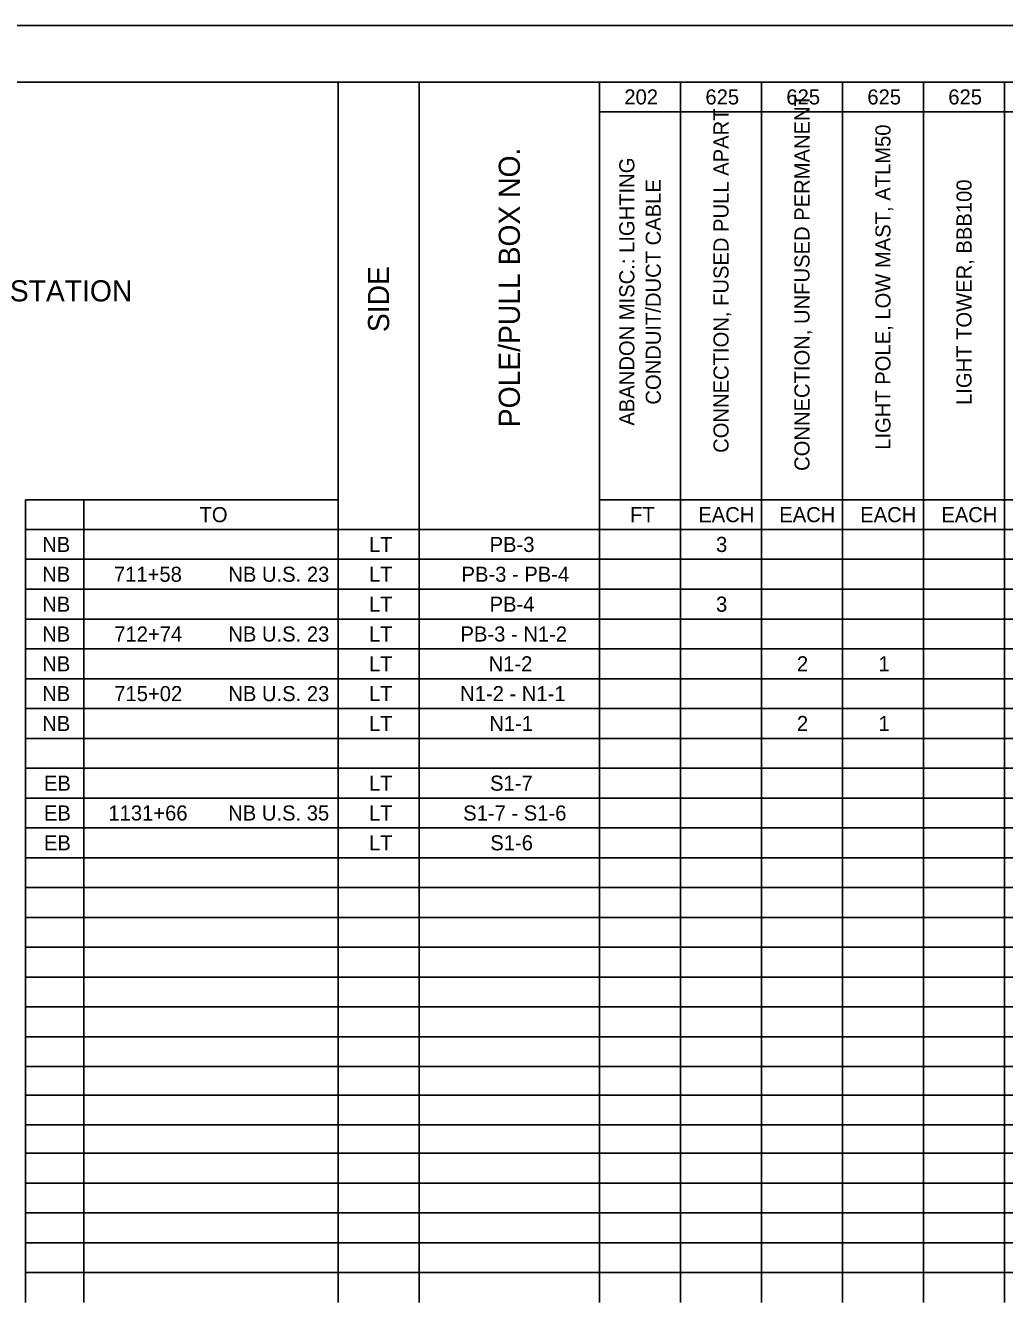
# Model space of a CAD drawing. Extents: x 0 to 34, y 0 to 22.
# Drawn here: x 4.68 to 13.35, y 10.69 to 22 of the extents above; entities that cross this region are included whole.
import ezdxf

# ---------------------------------------------------------------- set-up
doc = ezdxf.new("R2010")
doc.units = 0
for name, color, linetype in [('SH_Border', 7, 'Continuous'), ('SH_Cut_Line', 7, 'Continuous'), ('SH_Text', 7, 'Continuous')]:
    doc.layers.add(name, color=color, linetype=linetype)

msp = doc.modelspace()

# ---------------------------------------------------------------- linework, layer by layer
at = {"layer": 'SH_Border'}
msp.add_lwpolyline([(1.5, 21.5), (33.5, 21.5), (33.5, 0.5), (1.5, 0.5)], close=True, dxfattribs=at)
at = {"layer": 'SH_Cut_Line'}
msp.add_lwpolyline([(0, 0), (34, 0), (34, 22), (0, 22)], close=True, dxfattribs=at)
at = {"layer": 'SH_Text'}
for p, q in [((4.683, 21.5), (11.918, 21.5)), ((7.451, 21.5), (7.451, 21.236)), ((8.168, 21.5), (8.168, 21.236)), ((9.766, 21.5), (9.766, 21.236)), ((10.484, 21.5), (10.484, 21.236)), ((11.201, 21.5), (11.201, 21.236)), ((11.918, 21.5), (12.635, 21.5)), ((11.918, 21.5), (11.918, 21.236)), ((12.635, 21.5), (13.352, 21.5)), ((12.635, 21.5), (12.635, 21.236)), ((13.352, 21.5), (14.069, 21.5)), ((13.352, 21.5), (13.352, 21.236)), ((7.451, 21.236), (7.451, 20.972)), ((8.168, 21.236), (8.168, 20.972)), ((9.766, 21.236), (11.918, 21.236)), ((9.766, 21.236), (9.766, 20.972)), ((10.484, 21.236), (10.484, 20.972)), ((11.201, 21.236), (11.201, 20.972)), ((11.918, 21.236), (12.635, 21.236)), ((11.918, 21.236), (11.918, 20.972)), ((12.635, 21.236), (13.352, 21.236)), ((12.635, 21.236), (12.635, 20.972)), ((13.352, 21.236), (14.069, 21.236)), ((13.352, 21.236), (13.352, 20.972)), ((7.451, 20.972), (7.451, 20.707)), ((8.168, 20.972), (8.168, 20.707)), ((9.766, 20.972), (9.766, 20.707)), ((10.484, 20.972), (10.484, 20.707)), ((11.201, 20.972), (11.201, 20.707)), ((11.918, 20.972), (11.918, 20.707)), ((12.635, 20.972), (12.635, 20.707)), ((13.352, 20.972), (13.352, 20.707)), ((7.451, 20.707), (7.451, 20.443)), ((8.168, 20.707), (8.168, 20.443)), ((9.766, 20.707), (9.766, 20.443)), ((10.484, 20.707), (10.484, 20.443)), ((11.201, 20.707), (11.201, 20.443)), ((11.918, 20.707), (11.918, 20.443)), ((12.635, 20.707), (12.635, 20.443)), ((13.352, 20.707), (13.352, 20.443)), ((7.451, 20.443), (7.451, 20.179)), ((8.168, 20.443), (8.168, 20.179)), ((9.766, 20.443), (9.766, 20.179)), ((10.484, 20.443), (10.484, 20.179)), ((11.201, 20.443), (11.201, 20.179)), ((11.918, 20.443), (11.918, 20.179)), ((12.635, 20.443), (12.635, 20.179)), ((13.352, 20.443), (13.352, 20.179)), ((7.451, 20.179), (7.451, 19.915)), ((8.168, 20.179), (8.168, 19.915)), ((9.766, 20.179), (9.766, 19.915)), ((10.484, 20.179), (10.484, 19.915)), ((11.201, 20.179), (11.201, 19.915)), ((11.918, 20.179), (11.918, 19.915)), ((12.635, 20.179), (12.635, 19.915)), ((13.352, 20.179), (13.352, 19.915)), ((7.451, 19.915), (7.451, 19.651)), ((8.168, 19.915), (8.168, 19.651)), ((9.766, 19.915), (9.766, 19.651)), ((10.484, 19.915), (10.484, 19.651)), ((11.201, 19.915), (11.201, 19.651)), ((11.918, 19.915), (11.918, 19.651)), ((12.635, 19.915), (12.635, 19.651)), ((13.352, 19.915), (13.352, 19.651)), ((7.451, 19.651), (7.451, 19.386)), ((8.168, 19.651), (8.168, 19.386)), ((9.766, 19.651), (9.766, 19.386)), ((10.484, 19.651), (10.484, 19.386)), ((11.201, 19.651), (11.201, 19.386)), ((11.918, 19.651), (11.918, 19.386)), ((12.635, 19.651), (12.635, 19.386)), ((13.352, 19.651), (13.352, 19.386)), ((7.451, 19.386), (7.451, 19.122)), ((8.168, 19.386), (8.168, 19.122)), ((9.766, 19.386), (9.766, 19.122)), ((10.484, 19.386), (10.484, 19.122)), ((11.201, 19.386), (11.201, 19.122)), ((11.918, 19.386), (11.918, 19.122)), ((12.635, 19.386), (12.635, 19.122)), ((13.352, 19.386), (13.352, 19.122)), ((7.451, 19.122), (7.451, 18.858)), ((8.168, 19.122), (8.168, 18.858)), ((9.766, 19.122), (9.766, 18.858)), ((10.484, 19.122), (10.484, 18.858)), ((11.201, 19.122), (11.201, 18.858)), ((11.918, 19.122), (11.918, 18.858)), ((12.635, 19.122), (12.635, 18.858)), ((13.352, 19.122), (13.352, 18.858)), ((7.451, 18.858), (7.451, 18.594)), ((8.168, 18.858), (8.168, 18.594)), ((9.766, 18.858), (9.766, 18.594)), ((10.484, 18.858), (10.484, 18.594)), ((11.201, 18.858), (11.201, 18.594)), ((11.918, 18.858), (11.918, 18.594)), ((12.635, 18.858), (12.635, 18.594)), ((13.352, 18.858), (13.352, 18.594)), ((7.451, 18.594), (7.451, 18.329)), ((8.168, 18.594), (8.168, 18.329)), ((9.766, 18.594), (9.766, 18.329)), ((10.484, 18.594), (10.484, 18.329)), ((11.201, 18.594), (11.201, 18.329)), ((11.918, 18.594), (11.918, 18.329)), ((12.635, 18.594), (12.635, 18.329)), ((13.352, 18.594), (13.352, 18.329)), ((7.451, 18.329), (7.451, 18.065)), ((8.168, 18.329), (8.168, 18.065)), ((9.766, 18.329), (9.766, 18.065)), ((10.484, 18.329), (10.484, 18.065)), ((11.201, 18.329), (11.201, 18.065)), ((11.918, 18.329), (11.918, 18.065)), ((12.635, 18.329), (12.635, 18.065)), ((13.352, 18.329), (13.352, 18.065)), ((7.451, 18.065), (7.451, 17.801)), ((8.168, 18.065), (8.168, 17.801)), ((9.766, 18.065), (9.766, 17.801)), ((10.484, 18.065), (10.484, 17.801)), ((11.201, 18.065), (11.201, 17.801)), ((11.918, 18.065), (11.918, 17.801)), ((12.635, 18.065), (12.635, 17.801)), ((13.352, 18.065), (13.352, 17.801)), ((4.683, 17.801), (7.451, 17.801)), ((4.683, 17.801), (4.683, 17.537)), ((5.199, 17.801), (5.199, 17.537)), ((7.451, 17.801), (7.451, 17.537)), ((8.168, 17.801), (8.168, 17.537)), ((9.766, 17.801), (11.918, 17.801)), ((9.766, 17.801), (9.766, 17.537)), ((10.484, 17.801), (10.484, 17.537)), ((11.201, 17.801), (11.201, 17.537)), ((11.918, 17.801), (12.635, 17.801)), ((11.918, 17.801), (11.918, 17.537)), ((12.635, 17.801), (13.352, 17.801)), ((12.635, 17.801), (12.635, 17.537)), ((13.352, 17.801), (14.069, 17.801)), ((13.352, 17.801), (13.352, 17.537)), ((4.683, 17.537), (11.918, 17.537)), ((4.683, 17.537), (4.683, 17.273)), ((5.199, 17.537), (5.199, 17.273)), ((7.451, 17.537), (7.451, 17.273)), ((8.168, 17.537), (8.168, 17.273)), ((9.766, 17.537), (9.766, 17.273)), ((10.484, 17.537), (10.484, 17.273)), ((11.201, 17.537), (11.201, 17.273)), ((11.918, 17.537), (12.635, 17.537)), ((11.918, 17.537), (11.918, 17.273)), ((12.635, 17.537), (13.352, 17.537)), ((12.635, 17.537), (12.635, 17.273)), ((13.352, 17.537), (14.069, 17.537)), ((13.352, 17.537), (13.352, 17.273)), ((4.683, 17.273), (11.918, 17.273)), ((4.683, 17.273), (4.683, 17.008)), ((5.199, 17.273), (5.199, 17.008)), ((7.451, 17.273), (7.451, 17.008)), ((8.168, 17.273), (8.168, 17.008)), ((9.766, 17.273), (9.766, 17.008)), ((10.484, 17.273), (10.484, 17.008)), ((11.201, 17.273), (11.201, 17.008)), ((11.918, 17.273), (12.635, 17.273)), ((11.918, 17.273), (11.918, 17.008)), ((12.635, 17.273), (13.352, 17.273)), ((12.635, 17.273), (12.635, 17.008)), ((13.352, 17.273), (14.069, 17.273)), ((13.352, 17.273), (13.352, 17.008)), ((4.683, 17.008), (11.918, 17.008)), ((4.683, 17.008), (4.683, 16.744)), ((5.199, 17.008), (5.199, 16.744)), ((7.451, 17.008), (7.451, 16.744)), ((8.168, 17.008), (8.168, 16.744)), ((9.766, 17.008), (9.766, 16.744)), ((10.484, 17.008), (10.484, 16.744)), ((11.201, 17.008), (11.201, 16.744)), ((11.918, 17.008), (12.635, 17.008)), ((11.918, 17.008), (11.918, 16.744)), ((12.635, 17.008), (13.352, 17.008)), ((12.635, 17.008), (12.635, 16.744)), ((13.352, 17.008), (14.069, 17.008)), ((13.352, 17.008), (13.352, 16.744)), ((4.683, 16.744), (11.918, 16.744)), ((4.683, 16.744), (4.683, 16.48)), ((5.199, 16.744), (5.199, 16.48)), ((7.451, 16.744), (7.451, 16.48)), ((8.168, 16.744), (8.168, 16.48)), ((9.766, 16.744), (9.766, 16.48)), ((10.484, 16.744), (10.484, 16.48)), ((11.201, 16.744), (11.201, 16.48)), ((11.918, 16.744), (12.635, 16.744)), ((11.918, 16.744), (11.918, 16.48)), ((12.635, 16.744), (13.352, 16.744)), ((12.635, 16.744), (12.635, 16.48)), ((13.352, 16.744), (14.069, 16.744)), ((13.352, 16.744), (13.352, 16.48)), ((4.683, 16.48), (11.918, 16.48)), ((4.683, 16.48), (4.683, 16.216)), ((5.199, 16.48), (5.199, 16.216)), ((7.451, 16.48), (7.451, 16.216)), ((8.168, 16.48), (8.168, 16.216)), ((9.766, 16.48), (9.766, 16.216)), ((10.484, 16.48), (10.484, 16.216)), ((11.201, 16.48), (11.201, 16.216)), ((11.918, 16.48), (12.635, 16.48)), ((11.918, 16.48), (11.918, 16.216)), ((12.635, 16.48), (13.352, 16.48)), ((12.635, 16.48), (12.635, 16.216)), ((13.352, 16.48), (14.069, 16.48)), ((13.352, 16.48), (13.352, 16.216)), ((4.683, 16.216), (11.918, 16.216)), ((4.683, 16.216), (4.683, 15.951)), ((5.199, 16.216), (5.199, 15.951)), ((7.451, 16.216), (7.451, 15.951)), ((8.168, 16.216), (8.168, 15.951)), ((9.766, 16.216), (9.766, 15.951)), ((10.484, 16.216), (10.484, 15.951)), ((11.201, 16.216), (11.201, 15.951)), ((11.918, 16.216), (12.635, 16.216)), ((11.918, 16.216), (11.918, 15.951)), ((12.635, 16.216), (13.352, 16.216)), ((12.635, 16.216), (12.635, 15.951)), ((13.352, 16.216), (14.069, 16.216)), ((13.352, 16.216), (13.352, 15.951)), ((4.683, 15.951), (11.918, 15.951)), ((4.683, 15.951), (4.683, 15.687)), ((5.199, 15.951), (5.199, 15.687)), ((7.451, 15.951), (7.451, 15.687)), ((8.168, 15.951), (8.168, 15.687)), ((9.766, 15.951), (9.766, 15.687)), ((10.484, 15.951), (10.484, 15.687)), ((11.201, 15.951), (11.201, 15.687)), ((11.918, 15.951), (12.635, 15.951)), ((11.918, 15.951), (11.918, 15.687)), ((12.635, 15.951), (13.352, 15.951)), ((12.635, 15.951), (12.635, 15.687)), ((13.352, 15.951), (14.069, 15.951)), ((13.352, 15.951), (13.352, 15.687)), ((4.683, 15.687), (11.918, 15.687)), ((4.683, 15.687), (4.683, 15.423)), ((5.199, 15.687), (5.199, 15.423)), ((7.451, 15.687), (7.451, 15.423)), ((8.168, 15.687), (8.168, 15.423)), ((9.766, 15.687), (9.766, 15.423)), ((10.484, 15.687), (10.484, 15.423)), ((11.201, 15.687), (11.201, 15.423)), ((11.918, 15.687), (12.635, 15.687)), ((11.918, 15.687), (11.918, 15.423)), ((12.635, 15.687), (13.352, 15.687)), ((12.635, 15.687), (12.635, 15.423)), ((13.352, 15.687), (14.069, 15.687)), ((13.352, 15.687), (13.352, 15.423)), ((4.683, 15.423), (11.918, 15.423)), ((4.683, 15.423), (4.683, 15.159)), ((5.199, 15.423), (5.199, 15.159)), ((7.451, 15.423), (7.451, 15.159)), ((8.168, 15.423), (8.168, 15.159)), ((9.766, 15.423), (9.766, 15.159)), ((10.484, 15.423), (10.484, 15.159)), ((11.201, 15.423), (11.201, 15.159)), ((11.918, 15.423), (12.635, 15.423)), ((11.918, 15.423), (11.918, 15.159)), ((12.635, 15.423), (13.352, 15.423)), ((12.635, 15.423), (12.635, 15.159)), ((13.352, 15.423), (14.069, 15.423)), ((13.352, 15.423), (13.352, 15.159)), ((4.683, 15.159), (11.918, 15.159)), ((4.683, 15.159), (4.683, 14.895)), ((5.199, 15.159), (5.199, 14.895)), ((7.451, 15.159), (7.451, 14.895)), ((8.168, 15.159), (8.168, 14.895)), ((9.766, 15.159), (9.766, 14.895)), ((10.484, 15.159), (10.484, 14.895)), ((11.201, 15.159), (11.201, 14.895)), ((11.918, 15.159), (12.635, 15.159)), ((11.918, 15.159), (11.918, 14.895)), ((12.635, 15.159), (13.352, 15.159)), ((12.635, 15.159), (12.635, 14.895)), ((13.352, 15.159), (14.069, 15.159)), ((13.352, 15.159), (13.352, 14.895)), ((4.683, 14.895), (11.918, 14.895)), ((4.683, 14.895), (4.683, 14.63)), ((5.199, 14.895), (5.199, 14.63)), ((7.451, 14.895), (7.451, 14.63)), ((8.168, 14.895), (8.168, 14.63)), ((9.766, 14.895), (9.766, 14.63)), ((10.484, 14.895), (10.484, 14.63)), ((11.201, 14.895), (11.201, 14.63)), ((11.918, 14.895), (12.635, 14.895)), ((11.918, 14.895), (11.918, 14.63)), ((12.635, 14.895), (13.352, 14.895)), ((12.635, 14.895), (12.635, 14.63)), ((13.352, 14.895), (14.069, 14.895)), ((13.352, 14.895), (13.352, 14.63)), ((4.683, 14.63), (11.918, 14.63)), ((4.683, 14.63), (4.683, 14.366)), ((5.199, 14.63), (5.199, 14.366)), ((7.451, 14.63), (7.451, 14.366)), ((8.168, 14.63), (8.168, 14.366)), ((9.766, 14.63), (9.766, 14.366)), ((10.484, 14.63), (10.484, 14.366)), ((11.201, 14.63), (11.201, 14.366)), ((11.918, 14.63), (12.635, 14.63)), ((11.918, 14.63), (11.918, 14.366)), ((12.635, 14.63), (13.352, 14.63)), ((12.635, 14.63), (12.635, 14.366)), ((13.352, 14.63), (14.069, 14.63)), ((13.352, 14.63), (13.352, 14.366)), ((4.683, 14.366), (11.918, 14.366)), ((4.683, 14.366), (4.683, 14.102)), ((5.199, 14.366), (5.199, 14.102)), ((7.451, 14.366), (7.451, 14.102)), ((8.168, 14.366), (8.168, 14.102)), ((9.766, 14.366), (9.766, 14.102)), ((10.484, 14.366), (10.484, 14.102)), ((11.201, 14.366), (11.201, 14.102)), ((11.918, 14.366), (12.635, 14.366)), ((11.918, 14.366), (11.918, 14.102)), ((12.635, 14.366), (13.352, 14.366)), ((12.635, 14.366), (12.635, 14.102)), ((13.352, 14.366), (14.069, 14.366)), ((13.352, 14.366), (13.352, 14.102)), ((4.683, 14.102), (11.918, 14.102)), ((4.683, 14.102), (4.683, 13.838)), ((5.199, 14.102), (5.199, 13.838)), ((7.451, 14.102), (7.451, 13.838)), ((8.168, 14.102), (8.168, 13.838)), ((9.766, 14.102), (9.766, 13.838)), ((10.484, 14.102), (10.484, 13.838)), ((11.201, 14.102), (11.201, 13.838)), ((11.918, 14.102), (12.635, 14.102)), ((11.918, 14.102), (11.918, 13.838)), ((12.635, 14.102), (13.352, 14.102)), ((12.635, 14.102), (12.635, 13.838)), ((13.352, 14.102), (14.069, 14.102)), ((13.352, 14.102), (13.352, 13.838)), ((4.683, 13.838), (11.918, 13.838)), ((4.683, 13.838), (4.683, 13.573)), ((5.199, 13.838), (5.199, 13.573)), ((7.451, 13.838), (7.451, 13.573)), ((8.168, 13.838), (8.168, 13.573)), ((9.766, 13.838), (9.766, 13.573)), ((10.484, 13.838), (10.484, 13.573)), ((11.201, 13.838), (11.201, 13.573)), ((11.918, 13.838), (12.635, 13.838)), ((11.918, 13.838), (11.918, 13.573)), ((12.635, 13.838), (13.352, 13.838)), ((12.635, 13.838), (12.635, 13.573)), ((13.352, 13.838), (14.069, 13.838)), ((13.352, 13.838), (13.352, 13.573)), ((4.683, 13.573), (11.918, 13.573)), ((4.683, 13.573), (4.683, 13.309)), ((5.199, 13.573), (5.199, 13.309)), ((7.451, 13.573), (7.451, 13.309)), ((8.168, 13.573), (8.168, 13.309)), ((9.766, 13.573), (9.766, 13.309)), ((10.484, 13.573), (10.484, 13.309)), ((11.201, 13.573), (11.201, 13.309)), ((11.918, 13.573), (12.635, 13.573)), ((11.918, 13.573), (11.918, 13.309)), ((12.635, 13.573), (13.352, 13.573)), ((12.635, 13.573), (12.635, 13.309)), ((13.352, 13.573), (14.069, 13.573)), ((13.352, 13.573), (13.352, 13.309)), ((4.683, 13.309), (11.918, 13.309)), ((4.683, 13.309), (4.683, 13.045)), ((5.199, 13.309), (5.199, 13.045)), ((7.451, 13.309), (7.451, 13.045)), ((8.168, 13.309), (8.168, 13.045)), ((9.766, 13.309), (9.766, 13.045)), ((10.484, 13.309), (10.484, 13.045)), ((11.201, 13.309), (11.201, 13.045)), ((11.918, 13.309), (12.635, 13.309)), ((11.918, 13.309), (11.918, 13.045)), ((12.635, 13.309), (13.352, 13.309)), ((12.635, 13.309), (12.635, 13.045)), ((13.352, 13.309), (14.069, 13.309)), ((13.352, 13.309), (13.352, 13.045)), ((4.683, 13.045), (11.918, 13.045)), ((4.683, 13.045), (4.683, 12.781)), ((5.199, 13.045), (5.199, 12.781)), ((7.451, 13.045), (7.451, 12.781)), ((8.168, 13.045), (8.168, 12.781)), ((9.766, 13.045), (9.766, 12.781)), ((10.484, 13.045), (10.484, 12.781)), ((11.201, 13.045), (11.201, 12.781)), ((11.918, 13.045), (12.635, 13.045)), ((11.918, 13.045), (11.918, 12.781)), ((12.635, 13.045), (13.352, 13.045)), ((12.635, 13.045), (12.635, 12.781)), ((13.352, 13.045), (14.069, 13.045)), ((13.352, 13.045), (13.352, 12.781)), ((4.683, 12.781), (11.918, 12.781)), ((4.683, 12.781), (4.683, 12.265)), ((5.199, 12.781), (5.199, 12.265)), ((7.451, 12.781), (7.451, 12.265)), ((8.168, 12.781), (8.168, 12.265)), ((9.766, 12.781), (9.766, 12.265)), ((10.484, 12.781), (10.484, 12.265)), ((11.201, 12.781), (11.201, 12.265)), ((11.918, 12.781), (12.635, 12.781)), ((11.918, 12.781), (11.918, 12.265)), ((12.635, 12.781), (13.352, 12.781)), ((12.635, 12.781), (12.635, 12.265)), ((13.352, 12.781), (14.069, 12.781)), ((13.352, 12.781), (13.352, 12.265)), ((4.683, 12.529), (11.918, 12.529)), ((11.918, 12.529), (12.635, 12.529)), ((12.635, 12.529), (13.352, 12.529)), ((13.352, 12.529), (14.069, 12.529)), ((4.683, 12.265), (11.918, 12.265)), ((4.683, 12.265), (4.683, 11.749)), ((5.199, 12.265), (5.199, 11.749)), ((7.451, 12.265), (7.451, 11.749)), ((8.168, 12.265), (8.168, 11.749)), ((9.766, 12.265), (9.766, 11.749)), ((10.484, 12.265), (10.484, 11.749)), ((11.201, 12.265), (11.201, 11.749)), ((11.918, 12.265), (12.635, 12.265)), ((11.918, 12.265), (11.918, 11.749)), ((12.635, 12.265), (13.352, 12.265)), ((12.635, 12.265), (12.635, 11.749)), ((13.352, 12.265), (14.069, 12.265)), ((13.352, 12.265), (13.352, 11.749)), ((4.683, 12.013), (11.918, 12.013)), ((11.918, 12.013), (12.635, 12.013)), ((12.635, 12.013), (13.352, 12.013)), ((13.352, 12.013), (14.069, 12.013)), ((4.683, 11.749), (11.918, 11.749)), ((4.683, 11.749), (4.683, 11.485)), ((5.199, 11.749), (5.199, 11.485)), ((7.451, 11.749), (7.451, 11.485)), ((8.168, 11.749), (8.168, 11.485)), ((9.766, 11.749), (9.766, 11.485)), ((10.484, 11.749), (10.484, 11.485)), ((11.201, 11.749), (11.201, 11.485)), ((11.918, 11.749), (12.635, 11.749)), ((11.918, 11.749), (11.918, 11.485)), ((12.635, 11.749), (13.352, 11.749)), ((12.635, 11.749), (12.635, 11.485)), ((13.352, 11.749), (14.069, 11.749)), ((13.352, 11.749), (13.352, 11.485)), ((4.683, 11.485), (11.918, 11.485)), ((4.683, 11.485), (4.683, 11.221)), ((5.199, 11.485), (5.199, 11.221)), ((7.451, 11.485), (7.451, 11.221)), ((8.168, 11.485), (8.168, 11.221)), ((9.766, 11.485), (9.766, 11.221)), ((10.484, 11.485), (10.484, 11.221)), ((11.201, 11.485), (11.201, 11.221)), ((11.918, 11.485), (12.635, 11.485)), ((11.918, 11.485), (11.918, 11.221)), ((12.635, 11.485), (13.352, 11.485)), ((12.635, 11.485), (12.635, 11.221)), ((13.352, 11.485), (14.069, 11.485)), ((13.352, 11.485), (13.352, 11.221)), ((4.683, 11.221), (11.918, 11.221)), ((4.683, 11.221), (4.683, 10.956)), ((5.199, 11.221), (5.199, 10.956)), ((7.451, 11.221), (7.451, 10.956)), ((8.168, 11.221), (8.168, 10.956)), ((9.766, 11.221), (9.766, 10.956)), ((10.484, 11.221), (10.484, 10.956)), ((11.201, 11.221), (11.201, 10.956)), ((11.918, 11.221), (12.635, 11.221)), ((11.918, 11.221), (11.918, 10.956)), ((12.635, 11.221), (13.352, 11.221)), ((12.635, 11.221), (12.635, 10.956)), ((13.352, 11.221), (14.069, 11.221)), ((13.352, 11.221), (13.352, 10.956)), ((4.683, 10.956), (11.918, 10.956)), ((4.683, 10.956), (4.683, 10.692)), ((5.199, 10.956), (5.199, 10.692)), ((7.451, 10.956), (7.451, 10.692)), ((8.168, 10.956), (8.168, 10.692)), ((9.766, 10.956), (9.766, 10.692)), ((10.484, 10.956), (10.484, 10.692)), ((11.201, 10.956), (11.201, 10.692)), ((11.918, 10.956), (12.635, 10.956)), ((11.918, 10.956), (11.918, 10.692)), ((12.635, 10.956), (13.352, 10.956)), ((12.635, 10.956), (12.635, 10.692)), ((13.352, 10.956), (14.069, 10.956)), ((13.352, 10.956), (13.352, 10.692))]:
    msp.add_line(p, q, dxfattribs=at)

# ---------------------------------------------------------------- texts
for s, height, p in [('202', 0.1337, (9.986, 21.301)), ('625', 0.1337, (10.704, 21.301)), ('625', 0.1337, (11.421, 21.301)), ('625', 0.1337, (12.138, 21.301)), ('625', 0.1337, (12.855, 21.301)), ('STATION', 0.1872, (4.544, 19.557)), ('TO', 0.1337, (6.224, 17.602)), ('FT', 0.1337, (10.036, 17.602)), ('EACH', 0.1337, (10.641, 17.602)), ('EACH', 0.1337, (11.358, 17.602)), ('EACH', 0.1337, (12.075, 17.602)), ('EACH', 0.1337, (12.793, 17.602)), ('NB', 0.1337, (4.831, 17.338)), ('LT', 0.1337, (7.725, 17.338)), ('PB-3', 0.1337, (8.793, 17.338)), ('3', 0.134, (10.798, 17.338)), ('NB', 0.1337, (4.831, 17.074)), ('711+58', 0.1337, (5.466, 17.074)), ('NB U.S. 23', 0.1337, (6.479, 17.074)), ('LT', 0.1337, (7.725, 17.074)), ('PB-3 - PB-4', 0.13368, (8.544, 17.074)), ('NB', 0.1337, (4.831, 16.809)), ('LT', 0.1337, (7.725, 16.809)), ('PB-4', 0.1337, (8.793, 16.809)), ('3', 0.134, (10.798, 16.809)), ('NB', 0.1337, (4.831, 16.545)), ('712+74', 0.1337, (5.469, 16.545)), ('NB U.S. 23', 0.1337, (6.479, 16.545)), ('LT', 0.1337, (7.725, 16.545)), ('PB-3 - N1-2', 0.13368, (8.535, 16.545)), ('NB', 0.1337, (4.831, 16.281)), ('LT', 0.1337, (7.725, 16.281)), ('N1-2', 0.1337, (8.784, 16.281)), ('2', 0.134, (11.514, 16.281)), ('1', 0.134, (12.237, 16.281)), ('NB', 0.1337, (4.831, 16.017)), ('715+02', 0.1337, (5.469, 16.017)), ('NB U.S. 23', 0.1337, (6.479, 16.017)), ('LT', 0.1337, (7.725, 16.017)), ('N1-2 - N1-1', 0.13368, (8.532, 16.017)), ('NB', 0.1337, (4.831, 15.752)), ('LT', 0.1337, (7.725, 15.752)), ('N1-1', 0.1337, (8.79, 15.752)), ('2', 0.134, (11.514, 15.752)), ('1', 0.134, (12.237, 15.752)), ('EB', 0.1337, (4.846, 15.224)), ('LT', 0.1337, (7.725, 15.224)), ('S1-7', 0.1337, (8.797, 15.224)), ('EB', 0.1337, (4.846, 14.96)), ('1131+66', 0.1337, (5.417, 14.96)), ('NB U.S. 35', 0.1337, (6.478, 14.96)), ('LT', 0.1337, (7.725, 14.96)), ('S1-7 - S1-6', 0.13368, (8.559, 14.96)), ('EB', 0.1337, (4.846, 14.696)), ('LT', 0.1337, (7.725, 14.696)), ('S1-6', 0.1337, (8.799, 14.696))]:
    msp.add_text(s, height=height, dxfattribs=at).set_placement(p)
for s, height, p in [('CONNECTION, UNFUSED PERMANENT', 0.13368, (11.626, 18.056)), ('CONNECTION, FUSED PULL APART', 0.13368, (10.909, 18.216)), ('LIGHT POLE, LOW MAST, ATLM50', 0.13368, (12.343, 18.243)), ('POLE/PULL BOX NO.', 0.18716, (9.061, 18.443)), ('ABANDON MISC.: LIGHTING ', 0.13368, (10.075, 18.457)), ('CONDUIT/DUCT CABLE', 0.13368, (10.309, 18.643)), ('LIGHT TOWER, BBB100', 0.13368, (13.061, 18.64)), ('SIDE', 0.1872, (7.903, 19.285))]:
    msp.add_text(s, height=height, rotation=90, dxfattribs=at).set_placement(p)

doc.saveas('drawing.dxf')
